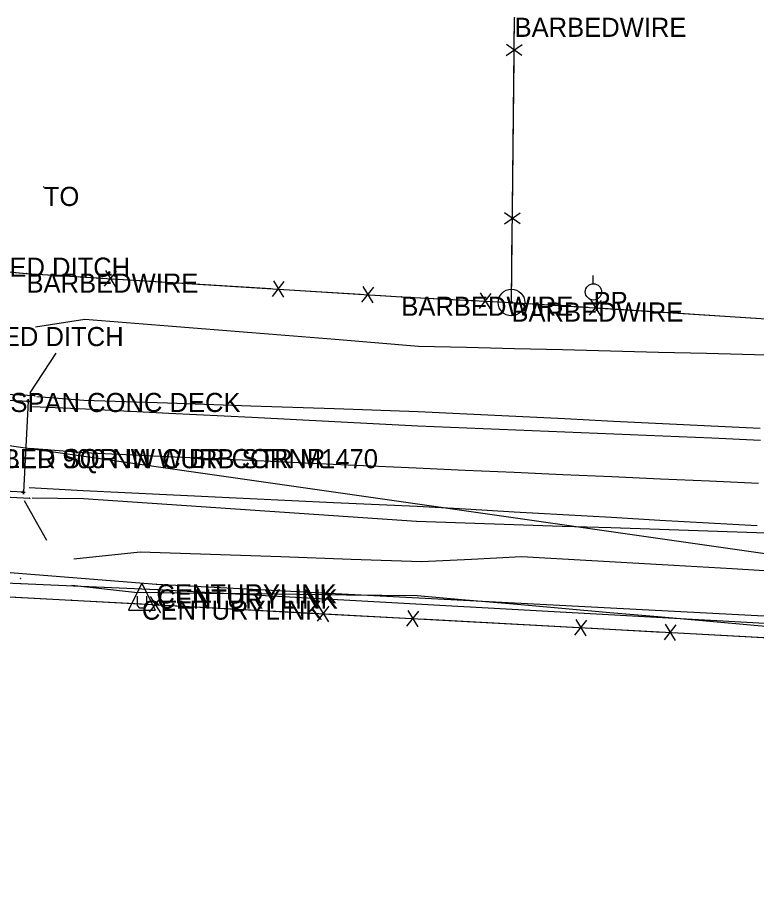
# Model space of a CAD drawing. Extents: x 675481 to 678499, y 212715 to 215285.
# Drawn here: x 677038 to 677231.3, y 214564.1 to 214793.3 of the extents above; entities that cross this region are included whole.
import ezdxf

# ---------------------------------------------------------------- set-up
doc = ezdxf.new("R2010")
doc.units = 0
for name, color, linetype in [('S_BASELINE', 7, 'Continuous'), ('S_BRIDGE', 7, 'Continuous'), ('S_BRIDGE_ANNOT', 7, 'Continuous'), ('S_DITCHLINE', 7, 'Continuous'), ('S_EDGE_PAVEMENT', 7, 'Continuous'), ('S_FENCE', 7, 'Continuous'), ('S_FENCE_ANNOT', 7, 'Continuous'), ('S_FIBER_OPTIC_CABLE', 7, 'Continuous'), ('S_FIBER_OPTIC_CABLE_ANNOT', 7, 'Continuous'), ('S_GRD_PT_SYM', 7, 'Continuous'), ('S_GUARDRAIL', 7, 'Continuous'), ('S_HEADWALL', 7, 'Continuous'), ('S_MISC_TOPO_POINT', 7, 'Continuous'), ('S_MSC_PT_SYM', 7, 'Continuous'), ('S_PAVEMENT_CROWN', 7, 'Continuous'), ('S_PRIMARY_CTL_ANNOT', 7, 'Continuous'), ('S_RDW_PT_SYM', 7, 'Continuous'), ('S_SHOULDER', 7, 'Continuous'), ('S_STR_PT_SYM', 7, 'Continuous'), ('S_UNDERGROUND_CABLE', 7, 'Continuous'), ('S_UTILITY_POLE', 7, 'Continuous'), ('S_UTILITY_POLE_ANNOT', 7, 'Continuous'), ('S_UTL_PT_SYM', 7, 'Continuous')]:
    doc.layers.add(name, color=color, linetype=linetype)

msp = doc.modelspace()

# ---------------------------------------------------------------- linework, layer by layer
at = {"layer": 'S_BASELINE'}
msp.add_line((676879.32, 214703.75), (677859.18, 214564.08), dxfattribs=at)
at = {"layer": 'S_BRIDGE'}
for p, q in [((677000.85, 214695.21), (677040.83, 214693.09)), ((677040.83, 214693.09), (677039.56, 214669.22)), ((677039.56, 214669.22), (676999.6, 214671.29))]:
    msp.add_line(p, q, dxfattribs=at)
at = {"layer": 'S_DITCHLINE'}
for points in [[(677042.74, 214712.48), (677055.66, 214714.49), (677077.46, 214712.74), (677099.26, 214710.98), (677121.06, 214709.22), (677142.85, 214707.46), (677155.41, 214707.15), (677167.97, 214706.84), (677180.52, 214706.53), (677193.08, 214706.21), (677205.64, 214705.9), (677218.2, 214705.59), (677230.75, 214705.28), (677243.31, 214704.97)], [(677052.77, 214651.81), (677070.09, 214653.67), (677088.49, 214653.03), (677106.89, 214652.4), (677125.29, 214651.76), (677143.69, 214651.13), (677156.76, 214651.78), (677169.83, 214652.43), (677188.21, 214651.37), (677206.58, 214650.31), (677224.95, 214649.26), (677243.32, 214648.2)], [(677052.19, 214644.92), (677068.57, 214643.1), (677087.07, 214642.88), (677105.57, 214642.67), (677124.08, 214642.45), (677142.58, 214642.24), (677155.17, 214641.13), (677167.75, 214640.03), (677180.34, 214638.92), (677192.93, 214637.82), (677205.51, 214636.71), (677218.1, 214635.61), (677230.68, 214634.5), (677243.27, 214633.4)]]:
    msp.add_lwpolyline(points, dxfattribs=at)
at = {"layer": 'S_EDGE_PAVEMENT'}
for points in [[(677041.9, 214691.64), (677055.84, 214691.04), (677077.56, 214689.94), (677099.29, 214688.84), (677121.02, 214687.74), (677142.74, 214686.64), (677155.55, 214686.11), (677168.35, 214685.57), (677181.16, 214685.03), (677193.96, 214684.49), (677206.76, 214683.95), (677219.57, 214683.42), (677232.37, 214682.88)], [(677041.1, 214670.52), (677055.18, 214669.67), (677077.01, 214668.64), (677098.84, 214667.62), (677120.67, 214666.6), (677142.51, 214665.58), (677155.21, 214664.86), (677167.92, 214664.14), (677180.62, 214663.42), (677193.33, 214662.69), (677206.04, 214661.97), (677218.74, 214661.25), (677231.45, 214660.53)]]:
    msp.add_lwpolyline(points, dxfattribs=at)
at = {"layer": 'S_FENCE'}
for p, q in [((677167.2, 214718.85), (677168.01, 214793.29)), ((677165.85, 214783.43), (677169.98, 214786.26)), ((677169.95, 214783.39), (677165.88, 214786.3)), ((677165.37, 214739.44), (677169.5, 214742.26)), ((677169.47, 214739.39), (677165.4, 214742.3)), ((676986.52, 214731.57), (677040.37, 214726.42)), ((677040.37, 214726.42), (677138.4, 214720.36)), ((677060.77, 214723.11), (677063.88, 214727.02)), ((677061.02, 214727.19), (677063.63, 214722.93)), ((677104.68, 214720.39), (677107.79, 214724.3)), ((677104.93, 214724.48), (677107.54, 214720.22)), ((677128.06, 214718.95), (677131.18, 214722.86)), ((677128.32, 214723.04), (677130.93, 214718.77)), ((677158.82, 214717.24), (677161.9, 214721.18)), ((677159.04, 214721.33), (677161.68, 214717.09)), ((677138.4, 214720.36), (677167.2, 214718.85)), ((677167.2, 214718.85), (677246.49, 214713.8)), ((677187.59, 214715.5), (677190.71, 214719.4)), ((677187.85, 214719.59), (677190.45, 214715.32)), ((676997.07, 214643.89), (677052.11, 214641.02)), ((677052.11, 214641.02), (677251.22, 214630.3)), ((677072.53, 214637.87), (677075.62, 214641.8)), ((677072.75, 214641.96), (677075.4, 214637.71)), ((677116.47, 214635.5), (677119.55, 214639.44)), ((677116.69, 214639.59), (677119.33, 214635.35)), ((677139.87, 214634.24), (677142.95, 214638.18)), ((677140.09, 214638.33), (677142.73, 214634.09)), ((677183.8, 214631.88), (677186.88, 214635.81)), ((677184.02, 214635.97), (677186.66, 214631.72)), ((677207.2, 214630.61), (677210.28, 214634.55)), ((677207.42, 214634.71), (677210.06, 214630.46))]:
    msp.add_line(p, q, dxfattribs=at)
for points in [[(677167.93, 214786.28), (677168.01, 214793.29)], [(677167.46, 214742.85), (677167.89, 214782.85)], [(677167.2, 214718.85), (677167.42, 214738.85)], [(677010.41, 214729.28), (677040.37, 214726.42)], [(677040.37, 214726.42), (677060.33, 214725.18)], [(677064.32, 214724.94), (677104.24, 214722.47)], [(677107.67, 214722.26), (677127.63, 214721.03)], [(677131.62, 214720.78), (677138.4, 214720.36)], [(677138.4, 214720.36), (677158.36, 214719.31)], [(677162.36, 214719.1), (677167.2, 214718.85)], [(677167.2, 214718.85), (677187.16, 214717.58)], [(677191.15, 214717.32), (677231.06, 214714.78)], [(677021.04, 214642.64), (677052.11, 214641.02)], [(677052.11, 214641.02), (677072.08, 214639.94)], [(677076.07, 214639.73), (677116.01, 214637.58)], [(677119.44, 214637.39), (677139.41, 214636.32)], [(677143.4, 214636.1), (677183.34, 214633.95)], [(677186.77, 214633.77), (677206.74, 214632.69)], [(677210.74, 214632.48), (677250.67, 214630.32)]]:
    msp.add_lwpolyline(points, dxfattribs=at)
for radius in [3.49, 0.247, 0.0349]:
    msp.add_circle((677167.2, 214718.85), radius, dxfattribs=at)
at = {"layer": 'S_FIBER_OPTIC_CABLE'}
for p, q in [((676936.82, 214656.1), (677074.33, 214645.17)), ((676933.93, 214650.27), (677038.82, 214645.4)), ((677038.82, 214645.4), (677074.57, 214643.84)), ((677074.33, 214645.17), (677249.36, 214636.13)), ((677074.57, 214643.84), (677249.23, 214634.11))]:
    msp.add_line(p, q, dxfattribs=at)
at = {"layer": 'S_GRD_PT_SYM'}
msp.add_lwpolyline([(677044.89, 214749.08), (677044.89, 214749.12), (677044.89, 214749.08), (677044.83, 214749.08), (677044.89, 214749.08), (677044.89, 214749.03), (677044.89, 214749.08), (677044.94, 214749.08)], dxfattribs=at)
at = {"layer": 'S_GUARDRAIL'}
for p, q in [((677042.56, 214694.4), (676999.23, 214696.58)), ((676997.65, 214670.04), (677041.23, 214667.66))]:
    msp.add_line(p, q, dxfattribs=at)
at = {"layer": 'S_HEADWALL'}
for points in [[(677041.37, 214695.24), (677048.13, 214705.57)], [(677045.69, 214656.63), (677039.87, 214666.98)]]:
    msp.add_lwpolyline(points, dxfattribs=at)
at = {"layer": 'S_MSC_PT_SYM'}
for points in [[(677168.01, 214793.29), (677168.01, 214793.34), (677168.01, 214793.29), (677167.95, 214793.29), (677168.01, 214793.29), (677168.01, 214793.24), (677168.01, 214793.29), (677168.06, 214793.29)], [(677040.37, 214726.42), (677040.37, 214726.47), (677040.37, 214726.42), (677040.32, 214726.42), (677040.37, 214726.42), (677040.37, 214726.37), (677040.37, 214726.42), (677040.42, 214726.42)], [(677138.4, 214720.36), (677138.4, 214720.41), (677138.4, 214720.36), (677138.34, 214720.36), (677138.4, 214720.36), (677138.4, 214720.31), (677138.4, 214720.36), (677138.45, 214720.36)], [(677167.2, 214718.85), (677167.2, 214718.9), (677167.2, 214718.85), (677167.15, 214718.85), (677167.2, 214718.85), (677167.2, 214718.8), (677167.2, 214718.85), (677167.25, 214718.85)], [(677167.2, 214718.85), (677167.2, 214718.9), (677167.2, 214718.85), (677167.15, 214718.85), (677167.2, 214718.85), (677167.2, 214718.8), (677167.2, 214718.85), (677167.25, 214718.85)], [(677052.11, 214641.02), (677052.11, 214641.07), (677052.11, 214641.02), (677052.06, 214641.02), (677052.11, 214641.02), (677052.11, 214640.97), (677052.11, 214641.02), (677052.16, 214641.02)]]:
    msp.add_lwpolyline(points, dxfattribs=at)
at = {"layer": 'S_PAVEMENT_CROWN'}
msp.add_lwpolyline([(677041.26, 214680.76), (677055.47, 214679.59), (677077.17, 214678.59), (677098.88, 214677.6), (677120.59, 214676.6), (677142.3, 214675.6), (677155.08, 214675.03), (677167.87, 214674.47), (677180.65, 214673.9), (677193.43, 214673.33), (677206.21, 214672.77), (677218.99, 214672.2), (677231.77, 214671.64)], dxfattribs=at)
at = {"layer": 'S_RDW_PT_SYM'}
for points in [[(677042.56, 214694.4), (677042.56, 214694.45), (677042.56, 214694.4), (677042.51, 214694.4), (677042.56, 214694.4), (677042.56, 214694.35), (677042.56, 214694.4), (677042.61, 214694.4)], [(677041.23, 214667.66), (677041.23, 214667.71), (677041.23, 214667.66), (677041.18, 214667.66), (677041.23, 214667.66), (677041.23, 214667.61), (677041.23, 214667.66), (677041.28, 214667.66)]]:
    msp.add_lwpolyline(points, dxfattribs=at)
at = {"layer": 'S_SHOULDER'}
for points in [[(677043.08, 214694.26), (677055.35, 214693.31), (677077.21, 214692.57), (677099.07, 214691.84), (677120.93, 214691.11), (677142.8, 214690.37), (677155.57, 214689.75), (677168.35, 214689.12), (677181.12, 214688.49), (677193.9, 214687.86), (677206.67, 214687.23), (677219.45, 214686.6), (677232.22, 214685.97)], [(677041.81, 214667.81), (677055.29, 214667.6), (677077.07, 214666.12), (677098.84, 214664.63), (677120.62, 214663.15), (677142.4, 214661.66), (677155.09, 214661.24), (677167.79, 214660.82), (677180.49, 214660.4), (677193.18, 214659.98), (677205.88, 214659.56), (677218.57, 214659.15), (677231.27, 214658.73), (677243.97, 214658.31)]]:
    msp.add_lwpolyline(points, dxfattribs=at)
at = {"layer": 'S_STR_PT_SYM'}
for points in [[(677040.83, 214693.09), (677040.83, 214693.59), (677040.83, 214693.09), (677040.33, 214693.09), (677040.83, 214693.09), (677040.83, 214692.59), (677040.83, 214693.09), (677041.33, 214693.09)], [(677039.56, 214669.22), (677039.56, 214669.72), (677039.56, 214669.22), (677039.06, 214669.22), (677039.56, 214669.22), (677039.56, 214668.72), (677039.56, 214669.22), (677040.06, 214669.22)]]:
    msp.add_lwpolyline(points, dxfattribs=at)
at = {"layer": 'S_UNDERGROUND_CABLE'}
for p, q in [((677070.56, 214645.46), (677067.03, 214638.37)), ((677070.56, 214645.46), (677074.05, 214638.37)), ((677069.36, 214639.61), (677069.36, 214642.05)), ((677071.72, 214642.05), (677071.72, 214639.61)), ((677067.03, 214638.37), (677074.05, 214638.37)), ((677069.98, 214638.95), (677069.36, 214639.61)), ((677071.18, 214638.95), (677069.98, 214638.95)), ((677071.72, 214639.61), (677071.18, 214638.95))]:
    msp.add_line(p, q, dxfattribs=at)
at = {"layer": 'S_UTILITY_POLE'}
msp.add_line((677188.53, 214723.76), (677188.53, 214725.87), dxfattribs=at)
msp.add_circle((677188.65, 214721.62), 2.13, dxfattribs=at)
at = {"layer": 'S_UTL_PT_SYM'}
for points in [[(677038.79, 214646.68), (677038.79, 214646.73), (677038.79, 214646.68), (677038.74, 214646.68), (677038.79, 214646.68), (677038.79, 214646.63), (677038.79, 214646.68), (677038.84, 214646.68)], [(677038.82, 214645.4), (677038.82, 214645.45), (677038.82, 214645.4), (677038.77, 214645.4), (677038.82, 214645.4), (677038.82, 214645.35), (677038.82, 214645.4), (677038.87, 214645.4)], [(677074.33, 214645.17), (677074.33, 214645.22), (677074.33, 214645.17), (677074.28, 214645.17), (677074.33, 214645.17), (677074.33, 214645.12), (677074.33, 214645.17), (677074.38, 214645.17)], [(677074.57, 214643.84), (677074.57, 214643.89), (677074.57, 214643.84), (677074.52, 214643.84), (677074.57, 214643.84), (677074.57, 214643.79), (677074.57, 214643.84), (677074.62, 214643.84)]]:
    msp.add_lwpolyline(points, dxfattribs=at)

# ---------------------------------------------------------------- texts
at = {"layer": 'S_BRIDGE_ANNOT'}
msp.add_text('L.M. 4.51 1 SPAN CONC DECK', height=5, dxfattribs=at).set_placement((677000.85, 214690.21))
at = {"layer": 'S_FENCE_ANNOT'}
for p in [(677168.01, 214788.29), (677040.37, 214721.42), (677138.4, 214715.36), (677167.2, 214713.85), (677167.2, 214713.85), (677167.2, 214713.85)]:
    msp.add_text('BARBEDWIRE', height=5, dxfattribs=at).set_placement(p)
at = {"layer": 'S_FIBER_OPTIC_CABLE_ANNOT'}
for p in [(677074.33, 214640.17), (677074.57, 214638.84)]:
    msp.add_text('CENTURYLINK', height=5, dxfattribs=at).set_placement(p)
at = {"layer": 'S_MISC_TOPO_POINT'}
for s, p in [('TO', (677044.89, 214744.08)), ('RIPRAP LINED DITCH', (676998.75, 214725.58)), ('RIPRAP LINED DITCH', (676997.03, 214707.44))]:
    msp.add_text(s, height=5, dxfattribs=at).set_placement(p)
at = {"layer": 'S_PRIMARY_CTL_ANNOT'}
for s, p in [('PD:NUMBER 900 NW CURB STR M1470', (677007.83, 214675.51)), ('PD:CHISLED SQR IN W BR CORNR', (677007.83, 214675.54))]:
    msp.add_text(s, height=5, dxfattribs=at).set_placement(p)
at = {"layer": 'S_UTILITY_POLE_ANNOT'}
for s, p in [('PP', (677188.65, 214716.62)), ('CENTURYLINK', (677070.56, 214635.92))]:
    msp.add_text(s, height=5, dxfattribs=at).set_placement(p)

doc.saveas('drawing.dxf')
